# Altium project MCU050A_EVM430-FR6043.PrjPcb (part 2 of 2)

## Sheet MCU050A_HID_Bridge.SchDoc
size 431 x 279 mm; Date: Not shown in title block; ApprovedBy: Not shown in title block; CheckedBy: Not shown in title block; Author: Not shown in title block; CompanyName: Not shown in title block; Engineer: Not shown in title block; Organization: Not shown in title block; Address1: Not shown in title block; Address2: Not shown in title block; Address3: Not shown in title block; Address4: Not shown in title block; DocumentNumber: 1; Revision: Use project parameter SCH_Rev; SheetNumber: 4; SheetTotal: 7; PageSetup: Record=PageOptions¦CenterHorizontal=True¦CenterVertical=True¦PrintScale=1.00¦XCorrection=1.00¦YCorrection=1.00¦PrintKind=0¦BorderSize=5000000¦LeftOffset=0¦BottomOffset=0¦Orientation=2¦PaperLength=1000¦PaperWidth=1000¦Scale=100¦PaperSource=15¦PrintQuality=600¦MediaType=1¦DitherType=10¦PaperKind=Letter¦PrintScaleMode=1
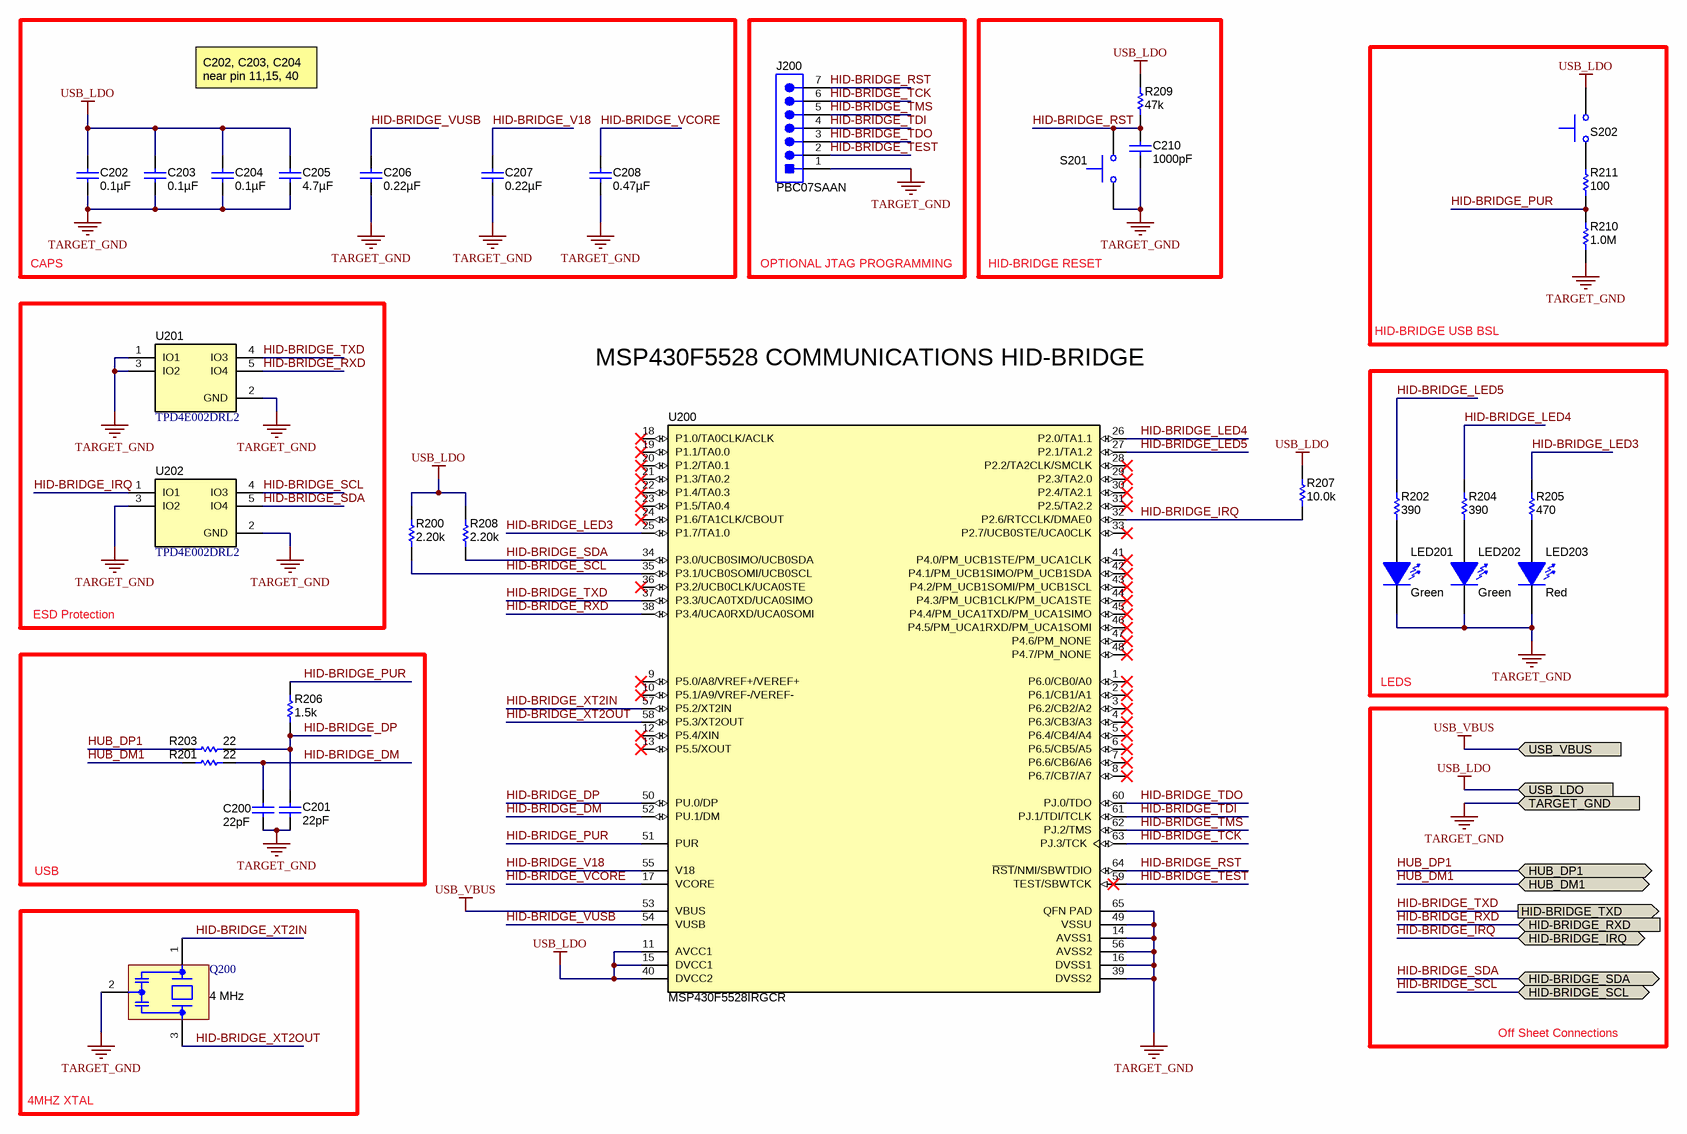
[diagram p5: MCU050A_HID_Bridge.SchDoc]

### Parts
C200  ValueDisplayed: 22pF  [0402S]  (hidden comment: GRM1555C1H220JA01D)
C201  ValueDisplayed: 22pF  [0402S]  (hidden comment: GRM1555C1H220JA01D)
C202  ValueDisplayed: 0.1µF  [0402S]  (hidden comment: GRM155R71C104KA88D)
C203  ValueDisplayed: 0.1µF  [0402S]  (hidden comment: GRM155R71C104KA88D)
C204  ValueDisplayed: 0.1µF  [0402S]  (hidden comment: GRM155R71C104KA88D)
C205  ValueDisplayed: 4.7µF  [0603S]  (hidden comment: GRM188R61A475MAAJ)
C206  ValueDisplayed: 0.22µF  [0402S]  (hidden comment: GRM155R71C224KA12D)
C207  ValueDisplayed: 0.22µF  [0402S]  (hidden comment: GRM155R71C224KA12D)
C208  ValueDisplayed: 0.47µF  [0402S]  (hidden comment: GRM155R61C474KE01)
C210  ValueDisplayed: 1000pF  [0402S]  (hidden comment: GRM1555C1H102JA01D)
J200  PBC07SAAN  [Sullins_xxC07SAAN]
LED201  value Green  [LTST-C191_Green]  (hidden comment: LTST-C191TGKT)
LED202  value Green  [LTST-C191_Green]  (hidden comment: LTST-C191TGKT)
LED203  value Red  [LED_LTST-C190_Red]  (hidden comment: LTST-C190CKT)
Q200  Frequency: 4 MHz  [Murata_CSTCR]  (hidden comment: CSTCR4M00G15L99-R0)
R200  ValueDisplayed: 2.20k  [0402S]  (hidden comment: CRCW04022K20FKED)
R201  ValueDisplayed: 22  [0402S]  (hidden comment: CRCW040222R0JNED)
R202  value 390  [0402S]  (hidden comment: CRCW0402390RJNED)
R203  ValueDisplayed: 22  [0402S]  (hidden comment: CRCW040222R0JNED)
R204  value 390  [0402S]  (hidden comment: CRCW0402390RJNED)
R205  ValueDisplayed: 470  [0402S]  (hidden comment: CRCW0402470RJNED)
R206  ValueDisplayed: 1.5k  [0402S]  (hidden comment: CRCW04021K50JNED)
R207  ValueDisplayed: 10.0k  [0603L]  (hidden comment: RCG060310K0FKEA)
R208  ValueDisplayed: 2.20k  [0402S]  (hidden comment: CRCW04022K20FKED)
R209  value 47k  [0402S]  (hidden comment: CRCW040247K0JNED)
R210  ValueDisplayed: 1.0M  [0402S]  (hidden comment: CRCW04021M00JNED)
R211  ValueDisplayed: 100  [0402S]  (hidden comment: CRCW0402100RJNED)
S201  TL1015AF160QG  [SW_TL1015AF160QG]  (value not drawn)
S202  TL1015AF160QG  [SW_TL1015AF160QG]  (value not drawn)
U200  MSP430F5528IRGCR  [RGC0064B]
U201  TPD4E002DRL2  [DRL0005A]
U202  TPD4E002DRL2  [DRL0005A]

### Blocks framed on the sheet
CAPS: C202-C208
OPTIONAL JTAG PROGRAMMING: J200
HID-BRIDGE RESET: C210 R209 S201
HID-BRIDGE USB BSL: R210 R211 S202
ESD Protection: U201 U202
LEDS: LED201-LED203 R202 R204 R205
USB: C200 C201 R201 R203 R206
4MHZ XTAL: Q200

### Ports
HID-BRIDGE_IRQ (bidir), HID-BRIDGE_RXD (in), HID-BRIDGE_SCL (bidir), HID-BRIDGE_SDA (bidir), HID-BRIDGE_TXD (out), HUB_DM1 (bidir), HUB_DP1 (bidir), TARGET_GND, USB_LDO, USB_VBUS

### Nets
TARGET_GND: C200.2 C201.2 C202.2 C203.2 C204.2 C205.2 C206.2 C207.2 C208.2 C210.2 J200.1 LED201.2(K) LED202.2(K) LED203.2(K) Q200.2(GND) R210.1 S201.1 U200.14(AVSS1) U200.16(DVSS1) U200.39(DVSS2) U200.49(VSSU) U200.56(AVSS2) U200.65(QFN_PAD) U201.1(IO1) U201.2(GND) U201.3(IO2) U202.2(GND) U202.3(IO2) ; port TARGET_GND
USB_LDO: C202.1 C203.1 C204.1 C205.1 R200.2 R207.2 R208.2 R209.2 S202.2 U200.11(AVCC1) U200.15(DVCC1) U200.40(DVCC2) ; port USB_LDO
USB_VBUS: U200.53(VBUS) ; port USB_VBUS
HID-BRIDGE_DM: C200.1 R201.2 U200.52(PU.1/DM)
HID-BRIDGE_DP: C201.1 R203.2 R206.1 U200.50(PU.0/DP)
HID-BRIDGE_IRQ: R207.1 U200.32(P2.6/RTCCLK/DMAE0) U202.1(IO1) ; port HID-BRIDGE_IRQ
HID-BRIDGE_LED3: R205.2 U200.25(P1.7/TA1.0)
HID-BRIDGE_LED4: R204.2 U200.26(P2.0/TA1.1)
HID-BRIDGE_LED5: R202.2 U200.27(P2.1/TA1.2)
HID-BRIDGE_PUR: R206.2 R210.2 R211.1 U200.51(PUR)
HID-BRIDGE_RST: C210.1 J200.7 R209.1 S201.2 U200.64(~{RST}/NMI/SBWTDIO)
HID-BRIDGE_RXD: U200.38(P3.4/UCA0RXD/UCA0SOMI) U201.5(IO4) ; port HID-BRIDGE_RXD
HID-BRIDGE_SCL: R200.1 U200.35(P3.1/UCB0SOMI/UCB0SCL) U202.4(IO3) ; port HID-BRIDGE_SCL
HID-BRIDGE_SDA: R208.1 U200.34(P3.0/UCB0SIMO/UCB0SDA) U202.5(IO4) ; port HID-BRIDGE_SDA
HID-BRIDGE_TCK: J200.6 U200.63(PJ.3/TCK)
HID-BRIDGE_TDI: J200.4 U200.61(PJ.1/TDI/TCLK)
HID-BRIDGE_TDO: J200.3 U200.60(PJ.0/TDO)
HID-BRIDGE_TEST: J200.2 U200.59(TEST/SBWTCK)
HID-BRIDGE_TMS: J200.5 U200.62(PJ.2/TMS)
HID-BRIDGE_TXD: U200.37(P3.3/UCA0TXD/UCA0SIMO) U201.4(IO3) ; port HID-BRIDGE_TXD
HID-BRIDGE_V18: C207.1 U200.55(V18)
HID-BRIDGE_VCORE: C208.1 U200.17(VCORE)
HID-BRIDGE_VUSB: C206.1 U200.54(VUSB)
HID-BRIDGE_XT2IN: Q200.1(In) U200.57(P5.2/XT2IN)
HID-BRIDGE_XT2OUT: Q200.3(Out) U200.58(P5.3/XT2OUT)
HUB_DM1: R201.1 ; port HUB_DM1
HUB_DP1: R203.1 ; port HUB_DP1
NetLED201_1: LED201.1(A) R202.1
NetLED202_1: LED202.1(A) R204.1
NetLED203_1: LED203.1(A) R205.1
NetR211_2: R211.2 S202.1

Not connected (* = marked no-connect by the designer): U200 1(P6.0/CB0/A0)* 2(P6.1/CB1/A1)* 3(P6.2/CB2/A2)* 4(P6.3/CB3/A3)* 5(P6.4/CB4/A4)* 6(P6.5/CB5/A5)* 7(P6.6/CB6/A6)* 8(P6.7/CB7/A7)* 9(P5.0/A8/VREF+/VEREF+)* 10(P5.1/A9/VREF-/VEREF-)* 12(P5.4/XIN)* 13(P5.5/XOUT)* 18(P1.0/TA0CLK/ACLK)* 19(P1.1/TA0.0)* 20(P1.2/TA0.1)* 21(P1.3/TA0.2)* 22(P1.4/TA0.3)* 23(P1.5/TA0.4)* 24(P1.6/TA1CLK/CBOUT)* 28(P2.2/TA2CLK/SMCLK)* 29(P2.3/TA2.0)* 30(P2.4/TA2.1)* 31(P2.5/TA2.2)* 33(P2.7/UCB0STE/UCA0CLK)* 36(P3.2/UCB0CLK/UCA0STE)* 41(P4.0/PM_UCB1STE/PM_UCA1CLK)* 42(P4.1/PM_UCB1SIMO/PM_UCB1SDA)* 43(P4.2/PM_UCB1SOMI/PM_UCB1SCL)* 44(P4.3/PM_UCB1CLK/PM_UCA1STE)* 45(P4.4/PM_UCA1TXD/PM_UCA1SIMO)* 46(P4.5/PM_UCA1RXD/PM_UCA1SOMI)* 47(P4.6/PM_NONE)* 48(P4.7/PM_NONE)*

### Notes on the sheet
- C202, C203, C204
  near pin 11,15, 40
- MSP430F5528 COMMUNICATIONS HID-BRIDGE
- Off Sheet Connections

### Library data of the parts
C200 C201 = GRM1555C1H220JA01D: CAP, CERM, 22 pF, 50 V, +/- 5%, C0G/NP0, 0402; Manufacturer: MuRata; Polarized: N; CompType: Capacitor; Value: 22pF; U/M: EA; Cap_F: 0.000000000022; Tolerance_%: 5; Value1: Unknown; VDC_V: 50; Value2: 50V; TaMin_C: -55; TaMax_C: 125; Cap_Case: 0402; AEC Category: Q200
C202-C204 = GRM155R71C104KA88D: CAP, CERM, 0.1 µF, 16 V, +/- 10%, X7R, 0402; Manufacturer: MuRata; Polarized: N; CompType: Capacitor; Value: 0.1uF; U/M: EA; Cap_F: 0.0000001; Tolerance_%: 10; Value1: Unknown; VDC_V: 16; Value2: 16V; TaMin_C: -55; TaMax_C: 125; Cap_Case: 0402
C205 = GRM188R61A475MAAJ: CAP, CERM, 4.7 µF, 10 V, +/- 20%, X5R, 0603; Manufacturer: MuRata; Polarized: N; CompType: Capacitor; Value: 4.7uF; U/M: EA; Cap_F: 0.0000047; Tolerance_%: 20; Value1: Unknown; VDC_V: 10; Value2: 10V; TaMin_C: -55; TaMax_C: 85; Cap_Case: 0603; AEC Category: Q200
C206 C207 = GRM155R71C224KA12D: CAP, CERM, 0.22 µF, 16 V, +/- 10%, X7R, 0402; Manufacturer: MuRata; Polarized: N; CompType: Capacitor; Value: 0.22uF; U/M: EA; Cap_F: 0.00000022; Tolerance_%: 10; Value1: Unknown; VDC_V: 16; Value2: 16V; TaMin_C: -55; TaMax_C: 125; Cap_Case: 0402
C208 = GRM155R61C474KE01: CAP, CERM, 0.47 µF, 16 V, +/- 10%, X5R, 0402; Manufacturer: MuRata; Polarized: N; CompType: Capacitor; Value: 0.47uF; U/M: EA; Cap_F: 0.00000047; Tolerance_%: 10; Value1: Unknown; VDC_V: 16; Value2: 16V; TaMin_C: -55; TaMax_C: 85; Cap_Case: 0402
C210 = GRM1555C1H102JA01D: CAP, CERM, 1000 pF, 50 V, +/- 5%, C0G/NP0, 0402; Manufacturer: MuRata; Polarized: N; CompType: Capacitor; Value: 1000pF; U/M: EA; Cap_F: 0.000000001; Tolerance_%: 5; Value1: Unknown; VDC_V: 50; Value2: 50V; TaMin_C: -55; TaMax_C: 125; Cap_Case: 0402
J200 = PBC07SAAN: Header, 2.54 mm, 7x1, Gold, TH; Manufacturer: Sullins Connector Solutions; SymbolCreator: a0411947; Pitch_mm: 2.54; Gender: Male; Shrouded: N; Row_Count: 1; Current_A: 3; Voltage_V: 1800; Cert_UL: Y
LED201 LED202 = LTST-C191TGKT: LED, Green, SMD; Manufacturer: Lite-On; Type: InGaN; Vf_V: 3.2; Value2: 3.2V; Io_A: 0.02; Value1: W; U/M: EA
LED203 = LTST-C190CKT: LED, Red, SMD; Manufacturer: Lite-On; Vf_V: 2; Value2: 2V; Io_A: 0.02; Tjmax_C: 85; Power_TotalModule: 0.0625; Value1: 0.0625W; U/M: EA
Q200 = CSTCR4M00G15L99-R0: Resonator, 4MHz, 39pF SMD; Manufacturer: MuRata; SymbolCreator: a0799721; U/M: EA; TaMin_C: 0; TaMax_C: 70; Frequency Stability: ±0.08 %
R200 R208 = CRCW04022K20FKED: RES, 2.20 k, 1%, 0.063 W, 0402; Manufacturer: Vishay-Dale; CompType: Resistor; Res_ohm: 2200; Value_Code: 2k20; Tolerance_%: 1; Power_W: 0.063; Value2: 0.063W; TempCo: 100 ppm/C; U/M: EA; Value: 2.20k; AEC Category: Q200
R201 R203 = CRCW040222R0JNED: RES, 22, 5%, 0.063 W, 0402; Manufacturer: Vishay-Dale; CompType: Resistor; Value: 22; Value_Code: 22R0; Tolerance_%: 5; Power_W: 0.063; Value2: 0.063W; VDC_V: 50; TempCo: 200 ppm/C; EIA_Code: E24; U/M: EA; AEC Category: Q200
R202 R204 = CRCW0402390RJNED: RES, 390 ohm, 5%, 0.063W, 0402; Manufacturer: Vishay-Dale; CompType: Resistor; Value_Code: 390R; Tolerance_%: 5; Power_W: 0.063; VDC_V: 50; TempCo: 200 ppm/C; EIA_Code: E24; U/M: EA
R205 = CRCW0402470RJNED: RES, 470, 5%, 0.063 W, 0402; Manufacturer: Vishay-Dale; CompType: Resistor; Value: 470; Value_Code: 470R; Tolerance_%: 5; Power_W: 0.063; Value2: 0.063W; VDC_V: 50; TempCo: 200 ppm/C; EIA_Code: E24; U/M: EA; AEC Category: Q200
R206 = CRCW04021K50JNED: RES, 1.5 k, 5%, 0.063 W, 0402; Manufacturer: Vishay-Dale; CompType: Resistor; Value: 1.5k; Res_ohm: 1500; Value_Code: 1k50; Tolerance_%: 5; Power_W: 0.063; Value2: 0.063W; VDC_V: 50; TempCo: 200 ppm/C; EIA_Code: E24; U/M: EA
R207 = RCG060310K0FKEA: RES, 10.0 k, 1%, 0.1 W, 0603; Manufacturer: Vishay Draloric; CompType: Resistor; Value: 10.0k; Res_ohm: 10000; Value_Code: 10k0; Tolerance_%: 1; Power_W: 0.1; Value2: 0.1W; VDC_V: 75; TempCo: 100 ppm/C; EIA_Code: E96; U/M: EA; AEC Category: Q200; AEC Qualified: N
R209 = CRCW040247K0JNED: RES, 47 k, 5%, 0.063 W, 0402; Manufacturer: Vishay-Dale; CompType: Resistor; Res_ohm: 47000; Value_Code: 47k0; Tolerance_%: 5; Power_W: 0.063; Value2: 0.063W; VDC_V: 50; TempCo: 200 ppm/C; EIA_Code: E24; U/M: EA
R210 = CRCW04021M00JNED: RES, 1.0 M, 5%, 0.063 W, 0402; Manufacturer: Vishay-Dale; CompType: Resistor; Value: 1.0Meg; Res_ohm: 1000000; Value_Code: 1M00; Tolerance_%: 5; Power_W: 0.063; Value2: 0.063W; VDC_V: 50; TempCo: 200 ppm/C; EIA_Code: E24; U/M: EA
R211 = CRCW0402100RJNED: RES, 100, 5%, 0.063 W, 0402; Manufacturer: Vishay-Dale; CompType: Resistor; Value: 100; Value_Code: 100R; Tolerance_%: 5; Power_W: 0.063; Value2: 0.063W; VDC_V: 50; TempCo: 200 ppm/C; EIA_Code: E24; U/M: EA
S201 S202 = TL1015AF160QG: Switch, Tactile, SPST-NO, 0.05A, 12V, SMT; Manufacturer: E-Switch; SymbolCreator: a0412235; VDC_V: 12; SwitchFunction: Off-Mom; PositionCount: 1; CurrentRating_mA: 50
U200 = MSP430F5528IRGCR: Mixed Signal MicroController, RGC0064B; Manufacturer: Texas Instruments; Alternate PartNumber: MSP430F5528IRGCT; ADC: 12-bit SAR; ADC Channels: 16; Brown Out Reset: Yes; DMA: 3; Eco-Plan: Green (RoHS & no Sb/Br); Flash(KB): 128; Frequency(MHz): 25; GPIO: 47; Multiplier: 32x32; SRAM(B): 8192; SubFamily: 5 Series; Timers - 16-bit: 4; USB: 1; USCI_A (UART/LIN/IrDA/SPI): 2; SymbolCreator: Altium/a0412235; CompType: IC; U/M: EA
U201 U202 = TPD4E002DRL2: Low-Capacitance Array with + / - 15 kV ESD Protection, 4 Channels, -40 to +85 degC, 5-pin SOT (DRL), Green (RoHS & no Sb/Br); Manufacturer: Texas Instruments; Alternate PartNumber: Equivalent; Breakdown Voltage(Min)(V): 6; IEC 61000-4-2 Air-Gap(+/- kV): 15; IO Capacitance(Typ)(pF): 11; IO Leakage Current(nA): 100; SubFamily: ESD Solution

## Sheet MCU050A_USB_Comm-USB_Power.SchDoc
size 431 x 279 mm; Date: Not shown in title block; ApprovedBy: Not shown in title block; CheckedBy: Not shown in title block; Author: Not shown in title block; CompanyName: Not shown in title block; Engineer: Not shown in title block; Organization: Not shown in title block; Address1: Not shown in title block; Address2: Not shown in title block; Address3: Not shown in title block; Address4: Not shown in title block; DocumentNumber: 1; Revision: Use project parameter SCH_Rev; SheetNumber: 5; SheetTotal: 7; PageSetup: Record=PageOptions¦CenterHorizontal=True¦CenterVertical=True¦PrintScale=1.00¦XCorrection=1.00¦YCorrection=1.00¦PrintKind=0¦BorderSize=5000000¦LeftOffset=0¦BottomOffset=0¦Orientation=2¦PaperLength=1000¦PaperWidth=1000¦Scale=100¦PaperSource=15¦PrintQuality=600¦MediaType=1¦DitherType=10¦PaperKind=Letter¦PrintScaleMode=1
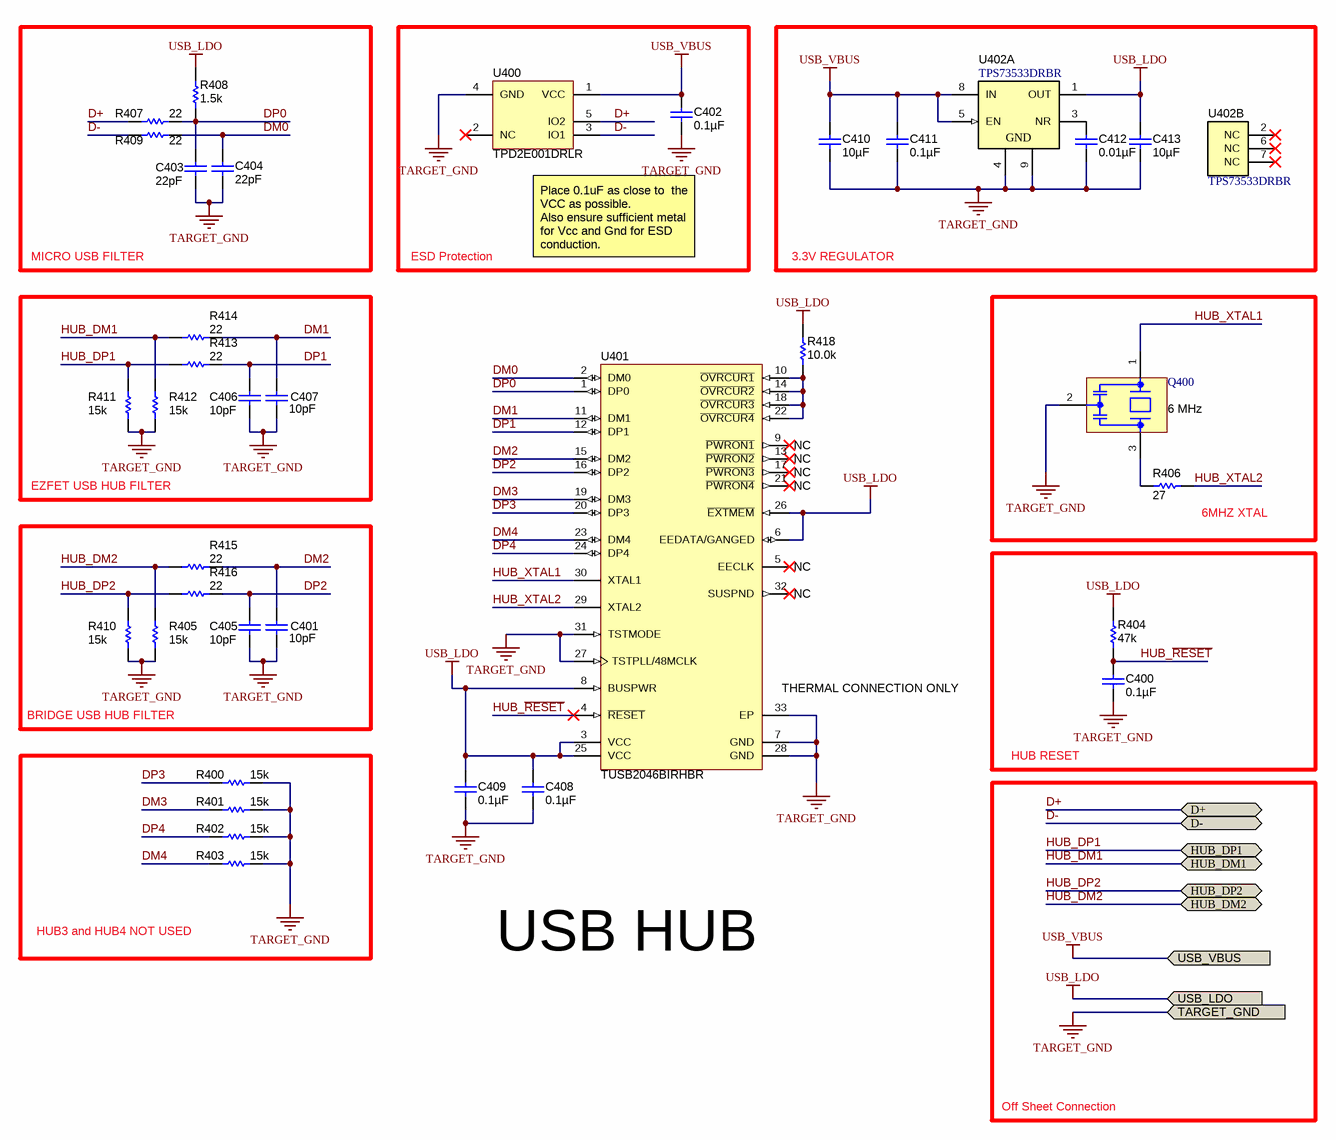
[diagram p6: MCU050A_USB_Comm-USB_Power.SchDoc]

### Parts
C400  ValueDisplayed: 0.1µF  [0402S]  (hidden comment: GRM155R71C104KA88D)
C401  ValueDisplayed: 10pF  [0402S]  (hidden comment: GRM1555C1H100JA01D)
C402  ValueDisplayed: 0.1µF  [0402S]  (hidden comment: GRM155R71C104KA88D)
C403  ValueDisplayed: 22pF  [0402S]  (hidden comment: GRM1555C1H220JA01D)
C404  ValueDisplayed: 22pF  [0402S]  (hidden comment: GRM1555C1H220JA01D)
C405  ValueDisplayed: 10pF  [0402S]  (hidden comment: GRM1555C1H100JA01D)
C406  ValueDisplayed: 10pF  [0402S]  (hidden comment: GRM1555C1H100JA01D)
C407  ValueDisplayed: 10pF  [0402S]  (hidden comment: GRM1555C1H100JA01D)
C408  ValueDisplayed: 0.1µF  [0402S]  (hidden comment: GRM155R71C104KA88D)
C409  ValueDisplayed: 0.1µF  [0402S]  (hidden comment: GRM155R71C104KA88D)
C410  ValueDisplayed: 10µF  [0603S]  (hidden comment: GRM188R61A106ME69D)
C411  ValueDisplayed: 0.1µF  [0402S]  (hidden comment: GRM155R71C104KA88D)
C412  ValueDisplayed: 0.01µF  [0402S]  (hidden comment: GRM155R71C103KA01D)
C413  ValueDisplayed: 10µF  [0603S]  (hidden comment: GRM188R61A106ME69D)
Q400  Frequency: 6 MHz  [Murata_CSTCR]  (hidden comment: CSTCR6M00G53Z-R0)
R400  ValueDisplayed: 15k  [0402S]  (hidden comment: CRCW040215K0JNED)
R401  ValueDisplayed: 15k  [0402S]  (hidden comment: CRCW040215K0JNED)
R402  ValueDisplayed: 15k  [0402S]  (hidden comment: CRCW040215K0JNED)
R403  ValueDisplayed: 15k  [0402S]  (hidden comment: CRCW040215K0JNED)
R404  value 47k  [0402S]  (hidden comment: CRCW040247K0JNED)
R405  ValueDisplayed: 15k  [0402S]  (hidden comment: CRCW040215K0JNED)
R406  value 27  [0402S]  (hidden comment: CRCW040227R0JNED)
R407  value 22  [0402S]  (hidden comment: CRCW040222R0JNED)
R408  value 1.5k  [0402S]  (hidden comment: CRCW04021K50JNED)
R409  value 22  [0402S]  (hidden comment: CRCW040222R0JNED)
R410  ValueDisplayed: 15k  [0402S]  (hidden comment: CRCW040215K0JNED)
R411  ValueDisplayed: 15k  [0402S]  (hidden comment: CRCW040215K0JNED)
R412  ValueDisplayed: 15k  [0402S]  (hidden comment: CRCW040215K0JNED)
R413  value 22  [0402S]  (hidden comment: CRCW040222R0JNED)
R414  value 22  [0402S]  (hidden comment: CRCW040222R0JNED)
R415  value 22  [0402S]  (hidden comment: CRCW040222R0JNED)
R416  value 22  [0402S]  (hidden comment: CRCW040222R0JNED)
R418  ValueDisplayed: 10.0k  [0603L]  (hidden comment: RCG060310K0FKEA)
U400  TPD2E001DRLR  [DRL0005A]
U401  TUSB2046BIRHBR  [RHB0032E]
U402  TPS73533DRBR  [DRB0008A]  (parts A,B of 2)

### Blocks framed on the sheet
MICRO USB FILTER: C403 C404 R407-R409
ESD Protection: C402 U400
3.3V REGULATOR: C410-C413 U402
EZFET USB HUB FILTER: C406 C407 R411-R414
6MHZ XTAL: Q400 R406
BRIDGE USB HUB FILTER: C401 C405 R405 R410 R415 R416
HUB RESET: C400 R404
HUB3 and HUB4 NOT USED: R400-R403

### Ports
D+ (bidir), D- (bidir), HUB_DM1 (bidir), HUB_DM2 (bidir), HUB_DP1 (bidir), HUB_DP2 (bidir), TARGET_GND, USB_LDO, USB_VBUS

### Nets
TARGET_GND: C400.2 C401.2 C402.2 C403.2 C404.2 C405.2 C406.2 C407.2 C408.2 C409.2 C410.2 C411.2 C412.2 C413.2 Q400.2(GND) R400.2 R401.2 R402.2 R403.2 R405.1 R410.1 R411.1 R412.1 U400.4(GND) U401.7(GND) U401.27(TSTPLL/48MCLK) U401.28(GND) U401.31(TSTMODE) U401.33(EP) U402.4(GND) U402.9(GND) ; port TARGET_GND
USB_LDO: C408.1 C409.1 C413.1 R404.2 R408.2 R418.2 U401.3(VCC) U401.6(EEDATA/GANGED) U401.8(BUSPWR) U401.25(VCC) U401.26(~{EXTMEM}) U402.1(OUT) ; port USB_LDO
USB_VBUS: C402.1 C410.1 C411.1 U400.1(VCC) U402.5(EN) U402.8(IN) ; port USB_VBUS
D+: R407.1 U400.5(IO2) ; port D+
D-: R409.1 U400.3(IO1) ; port D-
DM0: C404.1 R409.2 U401.2(DM0)
DM1: C407.1 R414.2 U401.11(DM1)
DM2: C401.1 R415.2 U401.15(DM2)
DM3: R401.1 U401.19(DM3)
DM4: R403.1 U401.23(DM4)
DP0: C403.1 R407.2 R408.1 U401.1(DP0)
DP1: C406.1 R413.2 U401.12(DP1)
DP2: C405.1 R416.2 U401.16(DP2)
DP3: R400.1 U401.20(DP3)
DP4: R402.1 U401.24(DP4)
HUB_DM1: R412.2 R414.1 ; port HUB_DM1
HUB_DM2: R405.2 R415.1 ; port HUB_DM2
HUB_DP1: R411.2 R413.1 ; port HUB_DP1
HUB_DP2: R410.2 R416.1 ; port HUB_DP2
HUB_~{RESET}: C400.1 R404.1 U401.4(~{RESET})
HUB_XTAL1: Q400.1(In) U401.30(XTAL1)
HUB_XTAL2: R406.2 U401.29(XTAL2)
NetC412_1: C412.1 U402.3(NR)
NetQ400_3: Q400.3(Out) R406.1
NetR418_1: R418.1 U401.10(~{OVRCUR1}) U401.14(~{OVRCUR2}) U401.18(~{OVRCUR3}) U401.22(~{OVRCUR4})

Not connected (* = marked no-connect by the designer): U400 2(NC)*; U401 5(EECLK)* 9(~{PWRON1})* 13(~{PWRON2})* 17(~{PWRON3})* 21(~{PWRON4})* 32(SUSPND)*; U402 2(NC)* 6(NC)* 7(NC)*

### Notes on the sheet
- Place 0.1uF as close to  the VCC as possible.
  Also ensure sufficient metal for Vcc and Gnd for ESD conduction.
- (near U401) NC
- (near U401) THERMAL CONNECTION ONLY
- USB HUB
- Off Sheet Connection

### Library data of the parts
C400 C402 C411 = GRM155R71C104KA88D: CAP, CERM, 0.1 µF, 16 V, +/- 10%, X7R, 0402; Manufacturer: MuRata; Polarized: N; CompType: Capacitor; Value: 0.1uF; U/M: EA; Cap_F: 0.0000001; Tolerance_%: 10; Value1: Unknown; VDC_V: 16; Value2: 16V; TaMin_C: -55; TaMax_C: 125; Cap_Case: 0402; AEC Category: Q200
C401 C405-C407 = GRM1555C1H100JA01D: CAP, CERM, 10 pF, 50 V, +/- 5%, C0G/NP0, 0402; Manufacturer: MuRata; Polarized: N; CompType: Capacitor; Value: 10pF; U/M: EA; Cap_F: 0.00000000001; Tolerance_%: 5; Value1: Unknown; VDC_V: 50; Value2: 50V; TaMin_C: -55; TaMax_C: 125; Cap_Case: 0402
C403 C404 = GRM1555C1H220JA01D: CAP, CERM, 22 pF, 50 V, +/- 5%, C0G/NP0, 0402; Manufacturer: MuRata; Polarized: N; CompType: Capacitor; Value: 22pF; U/M: EA; Cap_F: 0.000000000022; Tolerance_%: 5; Value1: Unknown; VDC_V: 50; Value2: 50V; TaMin_C: -55; TaMax_C: 125; Cap_Case: 0402
C408 C409 = GRM155R71C104KA88D: as C202 on sheet MCU050A_HID_Bridge
C410 C413 = GRM188R61A106ME69D: CAP, CERM, 10 µF, 10 V, +/- 20%, X5R, 0603; Manufacturer: MuRata; Polarized: N; CompType: Capacitor; Value: 10uF; U/M: EA; Cap_F: 0.00001; Tolerance_%: 20; Value1: Unknown; VDC_V: 10; Value2: 10V; TaMin_C: -55; TaMax_C: 85; Cap_Case: 0603; AEC Category: Q200; SizeArea_mm2: 1.28; SizeAreaWB_mm2: 4.68; SizeX_mm: 1.6; SizeY_mm: 0.8; SizeZ_mm: 1
C412 = GRM155R71C103KA01D: CAP, CERM, 0.01 µF, 16 V, +/- 10%, X7R, 0402; Manufacturer: MuRata; Polarized: N; CompType: Capacitor; Value: 0.01uF; U/M: EA; Cap_F: 0.00000001; Tolerance_%: 10; Value1: Unknown; VDC_V: 16; Value2: 16V; TaMin_C: -55; TaMax_C: 125; Cap_Case: 0402; AEC Category: Q200; SizeArea_mm2: 0.5; SizeAreaWB_mm2: 3; SizeX_mm: 1; SizeZ_mm: 0.6
Q400 = CSTCR6M00G53Z-R0: Resonator, 6MHz, 15pF SMD; Manufacturer: MuRata; SymbolCreator: a0799721; U/M: EA; TaMin_C: -40; TaMax_C: 125; Frequency Stability: ±0.2 %
R400-R403 R405 R410-R412 = CRCW040215K0JNED: RES, 15 k, 5%, 0.063 W, 0402; Manufacturer: Vishay-Dale; CompType: Resistor; Value: 15k; Res_ohm: 15000; Value_Code: 15k0; Tolerance_%: 5; Power_W: 0.063; Value2: 0.063W; VDC_V: 50; TempCo: 200 ppm/C; EIA_Code: E24; U/M: EA
R404 = CRCW040247K0JNED: as R209 on sheet MCU050A_HID_Bridge
R406 = CRCW040227R0JNED: RES, 27 ohm, 5%, 0.063W, 0402; Manufacturer: Vishay-Dale; CompType: Resistor; Value_Code: 27R0; Tolerance_%: 5; Power_W: 0.063; VDC_V: 50; TempCo: 200 ppm/C; EIA_Code: E24; U/M: EA
R407 R409 R413-R416 = CRCW040222R0JNED: RES, 22 ohm, 5%, 0.063W, 0402; Manufacturer: Vishay-Dale; CompType: Resistor; Value_Code: 22R0; Tolerance_%: 5; Power_W: 0.063; VDC_V: 50; TempCo: 200 ppm/C; EIA_Code: E24; U/M: EA
R408 = CRCW04021K50JNED: RES, 1.5 k, 5%, 0.063 W, 0402; Manufacturer: Vishay-Dale; CompType: Resistor; Res_ohm: 1500; Value_Code: 1k50; Tolerance_%: 5; Power_W: 0.063; Value2: 0.063W; VDC_V: 50; TempCo: 200 ppm/C; EIA_Code: E24; U/M: EA
R418 = RCG060310K0FKEA: as R207 on sheet MCU050A_HID_Bridge
U400 = TPD2E001DRLR: Low-Capacitance + / - 15 kV ESD-Protection Array for High-Speed Data Interfaces, 2 Channels, -40 to +85 degC, 5-pin SOT (DRL), Green (RoHS & no Sb/Br); Manufacturer: Texas Instruments; Alternate Manufacturer: None; Alternate PartNumber: Equivalent; Breakdown Voltage(Min)(V): 11; IEC 61000-4-2 Air-Gap(+/- kV): 15; IEC 61000-4-2 Contact(+/- kV): 8; IO Capacitance(Typ)(pF): 1.5; IO Leakage Current(nA): 1; SubFamily: ESD Solution; USB High Speed: TRUE
U401 = TUSB2046BIRHBR: 4-Port Full-Speed USB Hub, 3.3V, -40 to 85 degC, 32-Pin QFN (RHB), Green (RoHS & no Sb/Br); Manufacturer: Texas Instruments; Alternate Manufacturer: None; Alternate PartNumber: Equivalent; SubFamily: USB Hub Controller; USB Speed: Full; USB Full Speed: True; Supply Voltage(s)(V): 3.3
U402 = TPS73533DRBR: Single Output High PSRR LDO, 500 mA, Fixed 3.3 V Output, 2.7 to 6.5 V Input, with Low IQ, 8-pin SON (DRB), -40 to 125 degC, Green (RoHS & no Sb/Br); Manufacturer: Texas Instruments; Alternate PartNumber: Equivalent; Accuracy(%): 2; Fixed Output Options(V): 3.3; Iout(Max)(A): 0.5; Iq(Typ)(mA): 0.04; SubFamily: Single Channel LDO; Vdo(Typ)(mV): 280; Vin(Max)(V): 6.5; Vin(Min)(V): 2.7

## Sheet MCU050A_ezFET_Lite.SchDoc
size 431 x 279 mm; Date: Not shown in title block; ApprovedBy: Not shown in title block; CheckedBy: Not shown in title block; Author: Not shown in title block; CompanyName: Not shown in title block; Engineer: Not shown in title block; Organization: Not shown in title block; Address1: Not shown in title block; Address2: Not shown in title block; Address3: Not shown in title block; Address4: Not shown in title block; DocumentNumber: 1; Revision: Use project parameter SCH_Rev; SheetNumber: 6; SheetTotal: 7; PageSetup: Record=PageOptions¦CenterHorizontal=True¦CenterVertical=True¦PrintScale=1.00¦XCorrection=1.00¦YCorrection=1.00¦PrintKind=0¦BorderSize=5000000¦LeftOffset=0¦BottomOffset=0¦Orientation=2¦PaperLength=1000¦PaperWidth=1000¦Scale=100¦PaperSource=15¦PrintQuality=600¦MediaType=1¦DitherType=10¦PaperKind=Letter¦PrintScaleMode=1
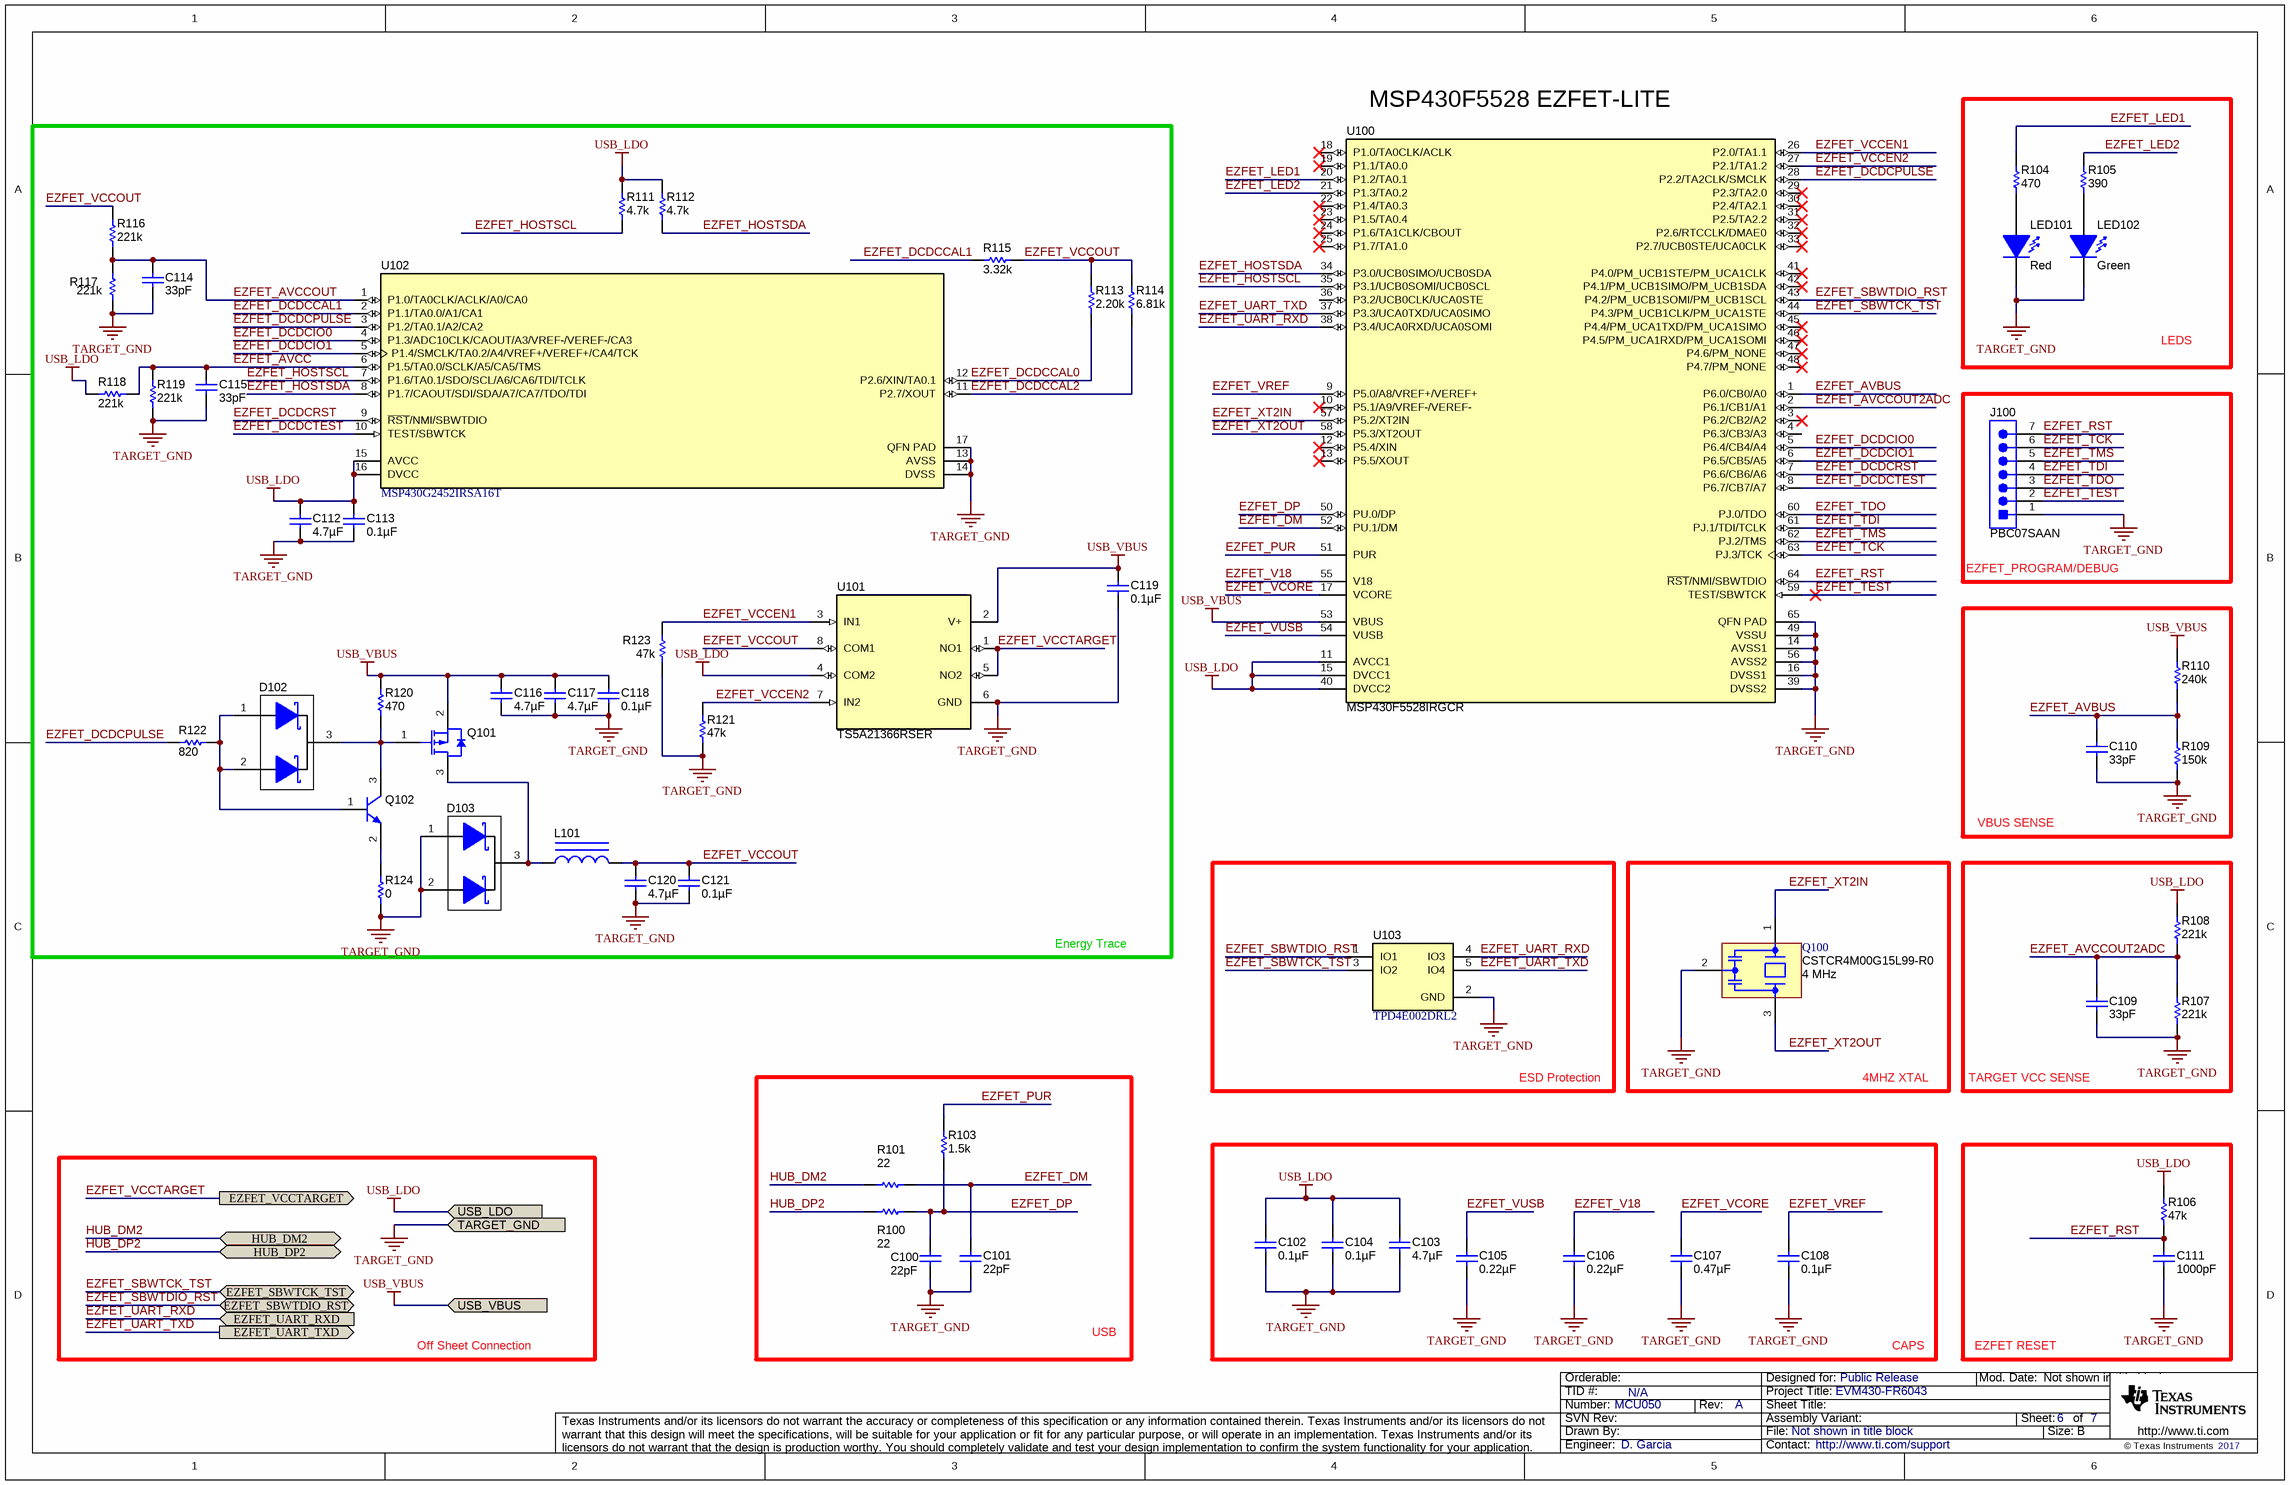
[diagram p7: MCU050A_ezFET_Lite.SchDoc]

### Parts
C100  ValueDisplayed: 22pF  [0402S]  (hidden comment: GRM1555C1H220JA01D)
C101  ValueDisplayed: 22pF  [0402S]  (hidden comment: GRM1555C1H220JA01D)
C102  ValueDisplayed: 0.1µF  [0402S]  (hidden comment: GRM155R71C104KA88D)
C103  ValueDisplayed: 4.7µF  [0603S]  (hidden comment: GRM188R61A475MAAJ)
C104  ValueDisplayed: 0.1µF  [0402S]  (hidden comment: GRM155R71C104KA88D)
C105  ValueDisplayed: 0.22µF  [0402S]  (hidden comment: GRM155R71C224KA12D)
C106  ValueDisplayed: 0.22µF  [0402S]  (hidden comment: GRM155R71C224KA12D)
C107  ValueDisplayed: 0.47µF  [0402S]  (hidden comment: GRM155R61C474KE01)
C108  ValueDisplayed: 0.1µF  [0402S]  (hidden comment: GRM155R71C104KA88D)
C109  ValueDisplayed: 33pF  [0402S]  (hidden comment: GRM1555C1H330JA01D)
C110  ValueDisplayed: 33pF  [0402S]  (hidden comment: GRM1555C1H330JA01D)
C111  ValueDisplayed: 1000pF  [0402S]  (hidden comment: GRM1555C1H102JA01D)
C112  ValueDisplayed: 4.7µF  [0603S]  (hidden comment: GRM188R61A475MAAJ)
C113  ValueDisplayed: 0.1µF  [0402S]  (hidden comment: GRM155R71C104KA88D)
C114  ValueDisplayed: 33pF  [0402S]  (hidden comment: GRM1555C1H330JA01D)
C115  ValueDisplayed: 33pF  [0402S]  (hidden comment: GRM1555C1H330JA01D)
C116  ValueDisplayed: 4.7µF  [0603S]  (hidden comment: GRM188R61A475MAAJ)
C117  ValueDisplayed: 4.7µF  [0603S]  (hidden comment: GRM188R61A475MAAJ)
C118  ValueDisplayed: 0.1µF  [0402S]  (hidden comment: GRM155R71C104KA88D)
C119  ValueDisplayed: 0.1µF  [0402S]  (hidden comment: GRM155R71C104KA88D)
C120  ValueDisplayed: 4.7µF  [0603S]  (hidden comment: GRM188R61A475MAAJ)
C121  ValueDisplayed: 0.1µF  [0402S]  (hidden comment: GRM155R71C104KA88D)
D102  BAS40-05-7-F  [SOT-23]  (value not drawn)
D103  BAS40-05-7-F  [SOT-23]  (value not drawn)
J100  PBC07SAAN  [Sullins_xxC07SAAN]
L101  CIG21L2R2MNE  [0805]  (value not drawn)
LED101  value Red  [LED_LTST-C190_Red]  (hidden comment: LTST-C190CKT)
LED102  value Green  [LTST-C191_Green]  (hidden comment: LTST-C191TGKT)
Q100  CSTCR4M00G15L99-R0  Frequency: 4 MHz  [Murata_CSTCR]
Q101  DMG1013UW  [SOT-323]  (value not drawn)
Q102  BC850CLT1G  [SOT-23]  (value not drawn)
R100  ValueDisplayed: 22  [0402S]  (hidden comment: CRCW040222R0JNED)
R101  ValueDisplayed: 22  [0402S]  (hidden comment: CRCW040222R0JNED)
R103  ValueDisplayed: 1.5k  [0402S]  (hidden comment: CRCW04021K50JNED)
R104  value 470  [0402S]  (hidden comment: CRCW0402470RJNED)
R105  value 390  [0402S]  (hidden comment: CRCW0402390RJNED)
R106  value 47k  [0402S]  (hidden comment: CRCW040247K0JNED)
R107  ValueDisplayed: 221k  [0402S]  (hidden comment: CRCW0402221KFKED)
R108  ValueDisplayed: 221k  [0402S]  (hidden comment: CRCW0402221KFKED)
R109  ValueDisplayed: 150k  [0402S]  (hidden comment: CRCW0402150KFKED)
R110  ValueDisplayed: 240k  [0402S]  (hidden comment: CRCW0402240KFKED)
R111  ValueDisplayed: 4.7k  [0402S]  (hidden comment: CRCW04024K70JNED)
R112  ValueDisplayed: 4.7k  [0402S]  (hidden comment: CRCW04024K70JNED)
R113  ValueDisplayed: 2.20k  [0402S]  (hidden comment: CRCW04022K20FKED)
R114  ValueDisplayed: 6.81k  [0402S]  (hidden comment: CRCW04026K81FKED)
R115  ValueDisplayed: 3.32k  [0402S]  (hidden comment: CRCW04023K32FKED)
R116  ValueDisplayed: 221k  [0402S]  (hidden comment: CRCW0402221KFKED)
R117  ValueDisplayed: 221k  [0402S]  (hidden comment: CRCW0402221KFKED)
R118  ValueDisplayed: 221k  [0402S]  (hidden comment: CRCW0402221KFKED)
R119  ValueDisplayed: 221k  [0402S]  (hidden comment: CRCW0402221KFKED)
R120  ValueDisplayed: 470  [0402S]  (hidden comment: CRCW0402470RJNED)
R121  ValueDisplayed: 47k  [0402S]  (hidden comment: CRCW040247K0JNED)
R122  ValueDisplayed: 820  [0402S]  (hidden comment: CRCW0402820RJNED)
R123  ValueDisplayed: 47k  [0402S]  (hidden comment: CRCW040247K0JNED)
R124  ValueDisplayed: 0  [0402S]  (hidden comment: CRCW04020000Z0ED)
U100  MSP430F5528IRGCR  [RGC0064B]
U101  TS5A21366RSER  [RSE0008A]
U102  MSP430G2452IRSA16T  [RSA0016B]
U103  TPD4E002DRL2  [DRL0005A]

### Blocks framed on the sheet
LEDS: LED101 LED102 R104 R105
Energy Trace: C112-C121 D102 D103 L101 Q101 Q102 R111-R124 U101 U102
EZFET_PROGRAM/DEBUG: J100
VBUS SENSE: C110 R109 R110
ESD Protection: U103
4MHZ XTAL: Q100
TARGET VCC SENSE: C109 R107 R108
USB: C100 C101 R100 R101 R103
CAPS: C102-C108
EZFET RESET: C111 R106

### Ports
EZFET_SBWTCK_TST (bidir), EZFET_SBWTDIO_RST (bidir), EZFET_UART_RXD (in), EZFET_UART_TXD (out), EZFET_VCCTARGET, HUB_DM2 (bidir), HUB_DP2 (bidir), TARGET_GND, USB_LDO, USB_VBUS

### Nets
TARGET_GND: C100.2 C101.2 C102.2 C103.2 C104.2 C105.2 C106.2 C107.2 C108.2 C109.2 C110.2 C111.2 C112.2 C113.2 C114.2 C115.2 C116.2 C117.2 C118.2 C119.2 C120.2 C121.2 D103.1(A) D103.2(K) J100.1 LED101.2(K) LED102.2(K) Q100.2(GND) R107.1 R109.1 R117.1 R119.1 R121.1 R123.1 R124.2 U100.14(AVSS1) U100.16(DVSS1) U100.39(DVSS2) U100.49(VSSU) U100.56(AVSS2) U100.65(QFN_PAD) U101.6(GND) U102.13(AVSS) U102.14(DVSS) U102.17(QFN_PAD) U103.2(GND) ; port TARGET_GND
USB_LDO: C102.1 C103.1 C104.1 C112.1 C113.1 R106.2 R108.2 R111.1 R112.1 R118.1 U100.11(AVCC1) U100.15(DVCC1) U100.40(DVCC2) U101.4(COM2) U102.15(AVCC) U102.16(DVCC) ; port USB_LDO
USB_VBUS: C116.1 C117.1 C118.1 C119.1 Q101.2(S) R110.2 R120.1 U100.53(VBUS) U101.2(V+) ; port USB_VBUS
EZFET_AVBUS: C110.1 R109.2 R110.1 U100.1(P6.0/CB0/A0)
EZFET_AVCC: C115.1 R118.2 R119.2 U102.6(P1.5/TA0.0/SCLK/A5/CA5/TMS)
EZFET_AVCCOUT: C114.1 R116.1 R117.2 U102.1(P1.0/TA0CLK/ACLK/A0/CA0)
EZFET_AVCCOUT2ADC: C109.1 R107.2 R108.1 U100.2(P6.1/CB1/A1)
EZFET_DCDCCAL0: R113.1 U102.12(P2.6/XIN/TA0.1)
EZFET_DCDCCAL1: R115.2 U102.2(P1.1/TA0.0/A1/CA1)
EZFET_DCDCCAL2: R114.1 U102.11(P2.7/XOUT)
EZFET_DCDCIO0: U100.5(P6.4/CB4/A4) U102.4(P1.3/ADC10CLK/CAOUT/A3/VREF-/VEREF-/CA3)
EZFET_DCDCIO1: U100.6(P6.5/CB5/A5) U102.5(P1.4/SMCLK/TA0.2/A4/VREF+/VEREF+/CA4/TCK)
EZFET_DCDCPULSE: R122.2 U100.28(P2.2/TA2CLK/SMCLK) U102.3(P1.2/TA0.1/A2/CA2)
EZFET_DCDCRST: U100.7(P6.6/CB6/A6) U102.9(~{RST}/NMI/SBWTDIO)
EZFET_DCDCTEST: U100.8(P6.7/CB7/A7) U102.10(TEST/SBWTCK)
EZFET_DM: C101.1 R101.2 U100.52(PU.1/DM)
EZFET_DP: C100.1 R100.2 R103.2 U100.50(PU.0/DP)
EZFET_HOSTSCL: R111.2 U100.35(P3.1/UCB0SOMI/UCB0SCL) U102.7(P1.6/TA0.1/SDO/SCL/A6/CA6/TDI/TCLK)
EZFET_HOSTSDA: R112.2 U100.34(P3.0/UCB0SIMO/UCB0SDA) U102.8(P1.7/CAOUT/SDI/SDA/A7/CA7/TDO/TDI)
EZFET_LED1: R104.2 U100.20(P1.2/TA0.1)
EZFET_LED2: R105.2 U100.21(P1.3/TA0.2)
EZFET_PUR: R103.1 U100.51(PUR)
EZFET_RST: C111.1 J100.7 R106.1 U100.64(~{RST}/NMI/SBWTDIO)
EZFET_SBWTCK_TST: U100.44(P4.3/PM_UCB1CLK/PM_UCA1STE) U103.3(IO2) ; port EZFET_SBWTCK_TST
EZFET_SBWTDIO_RST: U100.43(P4.2/PM_UCB1SOMI/PM_UCB1SCL) U103.1(IO1) ; port EZFET_SBWTDIO_RST
EZFET_TCK: J100.6 U100.63(PJ.3/TCK)
EZFET_TDI: J100.4 U100.61(PJ.1/TDI/TCLK)
EZFET_TDO: J100.3 U100.60(PJ.0/TDO)
EZFET_TEST: J100.2 U100.59(TEST/SBWTCK)
EZFET_TMS: J100.5 U100.62(PJ.2/TMS)
EZFET_UART_RXD: U100.38(P3.4/UCA0RXD/UCA0SOMI) U103.4(IO3) ; port EZFET_UART_RXD
EZFET_UART_TXD: U100.37(P3.3/UCA0TXD/UCA0SIMO) U103.5(IO4) ; port EZFET_UART_TXD
EZFET_V18: C106.1 U100.55(V18)
EZFET_VCCEN1: R123.2 U100.26(P2.0/TA1.1) U101.3(IN1)
EZFET_VCCEN2: R121.2 U100.27(P2.1/TA1.2) U101.7(IN2)
EZFET_VCCOUT: C120.1 C121.1 L101.2 R113.2 R114.2 R115.1 R116.2 U101.8(COM1)
EZFET_VCCTARGET: U101.1(NO1) U101.5(NO2) ; port EZFET_VCCTARGET
EZFET_VCORE: C107.1 U100.17(VCORE)
EZFET_VREF: C108.1 U100.9(P5.0/A8/VREF+/VEREF+)
EZFET_VUSB: C105.1 U100.54(VUSB)
EZFET_XT2IN: Q100.1(In) U100.57(P5.2/XT2IN)
EZFET_XT2OUT: Q100.3(Out) U100.58(P5.3/XT2OUT)
HUB_DM2: R101.1 ; port HUB_DM2
HUB_DP2: R100.1 ; port HUB_DP2
NetD102_1: D102.1(A) D102.2(K) Q102.1(B) R122.1
NetD102_3: D102.3(A) Q101.1(G) Q102.3(C) R120.2
NetD103_3: D103.3(A) L101.1 Q101.3(D)
NetLED101_1: LED101.1(A) R104.1
NetLED102_1: LED102.1(A) R105.1
NetQ102_2: Q102.2(E) R124.1

Not connected (* = marked no-connect by the designer): U100 3(P6.2/CB2/A2)* 4(P6.3/CB3/A3) 10(P5.1/A9/VREF-/VEREF-)* 12(P5.4/XIN)* 13(P5.5/XOUT)* 18(P1.0/TA0CLK/ACLK)* 19(P1.1/TA0.0)* 22(P1.4/TA0.3)* 23(P1.5/TA0.4)* 24(P1.6/TA1CLK/CBOUT)* 25(P1.7/TA1.0)* 29(P2.3/TA2.0)* 30(P2.4/TA2.1)* 31(P2.5/TA2.2)* 32(P2.6/RTCCLK/DMAE0)* 33(P2.7/UCB0STE/UCA0CLK)* 36(P3.2/UCB0CLK/UCA0STE) 41(P4.0/PM_UCB1STE/PM_UCA1CLK)* 42(P4.1/PM_UCB1SIMO/PM_UCB1SDA)* 45(P4.4/PM_UCA1TXD/PM_UCA1SIMO)* 46(P4.5/PM_UCA1RXD/PM_UCA1SOMI)* 47(P4.6/PM_NONE)* 48(P4.7/PM_NONE)*

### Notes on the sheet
- (near U100) MSP430F5528 EZFET-LITE
- Off Sheet Connection

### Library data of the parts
C100 C101 = GRM1555C1H220JA01D: as C200 on sheet MCU050A_HID_Bridge
C102 C104 C108 C113 C118 C119 C121 = GRM155R71C104KA88D: as C202 on sheet MCU050A_HID_Bridge
C103 C112 C116 C117 C120 = GRM188R61A475MAAJ: as C205 on sheet MCU050A_HID_Bridge
C105 C106 = GRM155R71C224KA12D: as C206 on sheet MCU050A_HID_Bridge
C107 = GRM155R61C474KE01: as C208 on sheet MCU050A_HID_Bridge
C109 C110 C114 C115 = GRM1555C1H330JA01D: CAP, CERM, 33 pF, 50 V, +/-5%, C0G/NP0, 0402; Manufacturer: MuRata; Polarized: N; CompType: Capacitor; Value: 33pF; U/M: EA; Cap_F: 0.000000000033; Tolerance_%: 5; Value1: Unknown; VDC_V: 50; Value2: 50V; TaMin_C: -55; TaMax_C: 125; Cap_Case: 0402
C111 = GRM1555C1H102JA01D: as C210 on sheet MCU050A_HID_Bridge
D102 D103 = BAS40-05-7-F: Diode, Schottky, 40V, 0.2A, SOT-23; Manufacturer: Diodes Inc.; SymbolCreator: a0412235; U/M: EA; Vf_V: 0.9; Value2: 0.9V; Io_A: 0.2; Vr_V: 40
J100 = PBC07SAAN: as J200 on sheet MCU050A_HID_Bridge
L101 = CIG21L2R2MNE: Inductor, Shielded, Composite, 2.2uH, 0.95A, 0.16 ohm, SMD; Manufacturer: Samsung; Ind_H: 2.2E-6; ValueDisplayed: 2.2µH; Imax_A: 0.95; Irms: 0.95A @ 40C rise; DCR_ohm: 0.16
LED101 = LTST-C190CKT: as LED203 on sheet MCU050A_HID_Bridge
LED102 = LTST-C191TGKT: as LED201 on sheet MCU050A_HID_Bridge
Q100 = CSTCR4M00G15L99-R0: as Q200 on sheet MCU050A_HID_Bridge
Q101 = BSS84W-7-F: MOSFET, P-CH, -50V, -0.13A, SOT-323; Manufacturer: Diodes Inc.; Alternate Manufacturer: None; U/M: EA; ChType: P; VdsMax_V: -50; Value1: 10 ohm; Rdson45_Ohm: 10; Value2: ? nC; Vgs_V: -20; IdsMax_A: -0.13
Q102 = BC850CLT1G, ON Semiconductor: Transistor, NPN, 45V, 0.1A, SOT-23; CompType: BJT; PNP: 0; NPN: 1; Vceo_V: 45; Vcesat1_V: 0.7; Value: 0.7V; IcRated_A: 0.1; HfeMax: 800; TaMin_C: -55; TaMax_C: 150; U/M: EA
R100 R101 = CRCW040222R0JNED: RES, 22, 5%, 0.063 W, 0402; Manufacturer: Vishay-Dale; CompType: Resistor; Value_Code: 22R0; Tolerance_%: 5; Power_W: 0.063; Value2: 0.063W; VDC_V: 50; TempCo: 200 ppm/C; EIA_Code: E24; U/M: EA; Value: 22; AEC Category: Q200
R103 = CRCW04021K50JNED: RES, 1.5 k, 5%, 0.063 W, 0402; Manufacturer: Vishay-Dale; CompType: Resistor; Res_ohm: 1500; Value_Code: 1k50; Tolerance_%: 5; Power_W: 0.063; Value2: 0.063W; VDC_V: 50; TempCo: 200 ppm/C; EIA_Code: E24; U/M: EA; Value: 1.5k
R104 = CRCW0402470RJNED: RES, 470, 5%, 0.063 W, 0402; Manufacturer: Vishay-Dale; CompType: Resistor; Value_Code: 470R; Tolerance_%: 5; Power_W: 0.063; Value2: 0.063W; VDC_V: 50; TempCo: 200 ppm/C; EIA_Code: E24; U/M: EA
R105 = CRCW0402390RJNED: as R202 on sheet MCU050A_HID_Bridge
R106 = CRCW040247K0JNED: as R209 on sheet MCU050A_HID_Bridge
R107 R108 R116-R119 = CRCW0402221KFKED: RES, 221 k, 1%, 0.063 W, 0402; Manufacturer: Vishay-Dale; CompType: Resistor; Res_ohm: 221000; Tolerance_%: 1; Power_W: 0.063; Value2: 0.063W; VDC_V: 50; TempCo: 100 ppm/C; EIA_Code: E96; U/M: EA; Value: 221k; AEC Category: Q200
R109 = CRCW0402150KFKED: RES, 150 k, 1%, 0.063 W, 0402; Manufacturer: Vishay-Dale; CompType: Resistor; Res_ohm: 150000; Tolerance_%: 1; Power_W: 0.063; Value2: 0.063W; VDC_V: 50; TempCo: 100 ppm/C; EIA_Code: E96; U/M: EA; Value: 150k; AEC Category: Q200
R110 = CRCW0402240KFKED: RES, 240 k, 1%, 0.063 W, 0402; Manufacturer: Vishay-Dale; CompType: Resistor; Res_ohm: 240000; Tolerance_%: 1; Power_W: 0.063; Value2: 0.063W; VDC_V: 50; TempCo: 100 ppm/C; U/M: EA; Value: 240k; AEC Category: Q200
R111 R112 = CRCW04024K70JNED: RES, 4.7 k, 5%, 0.063 W, 0402; Manufacturer: Vishay-Dale; CompType: Resistor; Res_ohm: 4700; Value_Code: 4k70; Tolerance_%: 5; Power_W: 0.063; Value2: 0.063W; VDC_V: 50; TempCo: 200 ppm/C; EIA_Code: E24; U/M: EA; Value: 4.7k
R113 = CRCW04022K20FKED: as R200 on sheet MCU050A_HID_Bridge
R114 = CRCW04026K81FKED: RES, 6.81 k, 1%, 0.063 W, 0402; Manufacturer: Vishay-Dale; CompType: Resistor; Res_ohm: 6810; Value_Code: 6k81; Tolerance_%: 1; Power_W: 0.063; Value2: 0.063W; VDC_V: 50; TempCo: 100 ppm/C; EIA_Code: E96; U/M: EA; Value: 6.81k; AEC Category: Q200
R115 = CRCW04023K32FKED: RES, 3.32 k, 1%, 0.063 W, 0402; Manufacturer: Vishay-Dale; CompType: Resistor; Res_ohm: 3320; Value_Code: 3k32; Tolerance_%: 1; Power_W: 0.063; Value2: 0.063W; VDC_V: 50; TempCo: 100 ppm/C; EIA_Code: E96; U/M: EA; Value: 3.32k; AEC Category: Q200
R120 = CRCW0402470RJNED: RES, 470, 5%, 0.063 W, 0402; Manufacturer: Vishay-Dale; CompType: Resistor; Value_Code: 470R; Tolerance_%: 5; Power_W: 0.063; Value2: 0.063W; VDC_V: 50; TempCo: 200 ppm/C; EIA_Code: E24; U/M: EA; Value: 470
R121 R123 = CRCW040247K0JNED: RES, 47 k, 5%, 0.063 W, 0402; Manufacturer: Vishay-Dale; CompType: Resistor; Res_ohm: 47000; Value_Code: 47k0; Tolerance_%: 5; Power_W: 0.063; Value2: 0.063W; VDC_V: 50; TempCo: 200 ppm/C; EIA_Code: E24; U/M: EA; Value: 47k
R122 = CRCW0402820RJNED: RES, 820, 5%, 0.063 W, 0402; Manufacturer: Vishay-Dale; CompType: Resistor; Value_Code: 820R; Tolerance_%: 5; Power_W: 0.063; Value2: 0.063W; VDC_V: 50; TempCo: 200 ppm/C; EIA_Code: E24; U/M: EA; Value: 820
R124 = CRCW04020000Z0ED: RES, 0, 5%, 0.063 W, 0402; Manufacturer: Vishay-Dale; CompType: Resistor; Value_Code: 0000; Tolerance_%: 5; Power_W: 0.063; Value2: 0.063W; VDC_V: 50; TempCo: 200 ppm/C; EIA_Code: E24; U/M: EA; Value: 0
U100 = MSP430F5528IRGCR: as U200 on sheet MCU050A_HID_Bridge
U101 = CMP-0074338-2: 0.75-Ohm DUAL SPST ANALOG SWITCH WITH 1.8-V COMPATIBLE INPUT LOGIC, RSE0008A (UQFN-8); Manufacturer: Texas Instruments; SizeZ_mm: 0.6; SizeX_mm: 1.5; SizeArea_mm2: 2.25; CompType: IC; U/M: EA; SizeAreaWB_mm2: 6.25
U102 = CMP-0039612-1: 16 MHz Mixed Signal Microcontroller with 8 KB Flash, 256 B SRAM and 16 GPIOs, 16-pin QFN (RSA), Green (RoHS & no Sb/Br); Manufacturer: Texas Instruments; GPIO: 16; Cap touch I/O: Yes; SRAM(B): 256; ADC: 10-bit SAR; Timers - 16-bit: 1; USI: "(I2C/SPI)","1"; SubFamily: Value Line; ADC Channels: 8
U103 = TPD4E002DRL2: as U201 on sheet MCU050A_HID_Bridge

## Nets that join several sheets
EZ-FET_VCC: MCU050A_EVM430-FR6043 (J2.1), MCU050A_main (S5.3)
TARGET_GND: MCU050A_EVM430-FR6043 (J2.3 J2.4 J12.5 RUSB.1), MCU050A_main (36 pins), MCU050A_HID_Bridge (28 pins), MCU050A_USB_Comm-USB_Power (31 pins), MCU050A_ezFET_Lite (46 pins)
TARGET_VCC: MCU050A_main (J32.1 S5.2), MCU050A_Analog-Front-End (JP3.2)
USB_LDO: MCU050A_EVM430-FR6043 (J4.3), MCU050A_HID_Bridge (12 pins), MCU050A_USB_Comm-USB_Power (12 pins), MCU050A_ezFET_Lite (16 pins)
USB_VBUS: MCU050A_EVM430-FR6043 (J12.1), MCU050A_HID_Bridge (U200.53), MCU050A_USB_Comm-USB_Power (6 pins), MCU050A_ezFET_Lite (9 pins)
USS_GND: MCU050A_main (13 pins), MCU050A_Analog-Front-End (44 pins)
CH0_IN: MCU050A_main (U1.74), MCU050A_Analog-Front-End (R75.1)
CH0_OUT: MCU050A_main (U1.73), MCU050A_Analog-Front-End (R77.1)
CH1_IN: MCU050A_main (U1.67), MCU050A_Analog-Front-End (R80.1)
CH1_OUT: MCU050A_main (U1.68), MCU050A_Analog-Front-End (R78.1)
COMM_IRQ: MCU050A_EVM430-FR6043 (J1.1), MCU050A_main (U1.31)
COMM_RXD: MCU050A_EVM430-FR6043 (J1.7), MCU050A_main (R56.1)
COMM_SCL: MCU050A_EVM430-FR6043 (J1.3), MCU050A_main (R11.1 R30.1 U1.30)
COMM_SDA: MCU050A_EVM430-FR6043 (J1.5), MCU050A_main (R12.1 R31.1 U1.29)
COMM_TXD: MCU050A_EVM430-FR6043 (J1.9), MCU050A_main (R57.1)
D+: MCU050A_EVM430-FR6043 (J12.3), MCU050A_USB_Comm-USB_Power (R407.1 U400.5)
D-: MCU050A_EVM430-FR6043 (J12.2), MCU050A_USB_Comm-USB_Power (R409.1 U400.3)
EZFET_SBWTCK_TST: MCU050A_EVM430-FR6043 (R126.1), MCU050A_ezFET_Lite (U100.44 U103.3)
EZFET_SBWTDIO_RST: MCU050A_EVM430-FR6043 (R125.1), MCU050A_ezFET_Lite (U100.43 U103.1)
EZFET_UART_RXD: MCU050A_EVM430-FR6043 (R128.1), MCU050A_ezFET_Lite (U100.38 U103.4)
EZFET_UART_TXD: MCU050A_EVM430-FR6043 (R127.1), MCU050A_ezFET_Lite (U100.37 U103.5)
EZFET_VCCTARGET: MCU050A_EVM430-FR6043 (J4.1), MCU050A_ezFET_Lite (U101.1 U101.5)
HID-BRIDGE_IRQ: MCU050A_EVM430-FR6043 (R212.1), MCU050A_HID_Bridge (R207.1 U200.32 U202.1)
HID-BRIDGE_RXD: MCU050A_EVM430-FR6043 (R216.1), MCU050A_HID_Bridge (U200.38 U201.5)
HID-BRIDGE_SCL: MCU050A_EVM430-FR6043 (R213.1), MCU050A_HID_Bridge (R200.1 U200.35 U202.4)
HID-BRIDGE_SDA: MCU050A_EVM430-FR6043 (R214.1), MCU050A_HID_Bridge (R208.1 U200.34 U202.5)
HID-BRIDGE_TXD: MCU050A_EVM430-FR6043 (R215.1), MCU050A_HID_Bridge (U200.37 U201.4)
HUB_DM1: MCU050A_HID_Bridge (R201.1), MCU050A_USB_Comm-USB_Power (R412.2 R414.1)
HUB_DM2: MCU050A_USB_Comm-USB_Power (R405.2 R415.1), MCU050A_ezFET_Lite (R101.1)
HUB_DP1: MCU050A_HID_Bridge (R203.1), MCU050A_USB_Comm-USB_Power (R411.2 R413.1)
HUB_DP2: MCU050A_USB_Comm-USB_Power (R410.2 R416.1), MCU050A_ezFET_Lite (R100.1)
JTAG_RESET: MCU050A_EVM430-FR6043 (J3.1), MCU050A_main (5 pins)
JTAG_RXD: MCU050A_EVM430-FR6043 (J3.5), MCU050A_main (J34.14 R41.1)
JTAG_TEST: MCU050A_EVM430-FR6043 (J3.3), MCU050A_main (J34.8 U1.15)
JTAG_TXD: MCU050A_EVM430-FR6043 (J3.7), MCU050A_main (J34.12 R40.1)
RxEn: MCU050A_main (U1.62), MCU050A_Analog-Front-End (J10.4 R68.2)
RxPwr: MCU050A_main (U1.2), MCU050A_Analog-Front-End (J10.3 R72.2)
RxSel1: MCU050A_main (U1.75), MCU050A_Analog-Front-End (J10.6 R70.2)
RxSel2: MCU050A_main (U1.76), MCU050A_Analog-Front-End (J10.8 R69.1)
Tx5vEn: MCU050A_main (U1.5), MCU050A_Analog-Front-End (J10.1 R73.2)
TxPwr: MCU050A_main (U1.4), MCU050A_Analog-Front-End (J10.7 R71.2)
TxSel: MCU050A_main (U1.3), MCU050A_Analog-Front-End (J10.5)
XPB0: MCU050A_main (U1.55), MCU050A_Analog-Front-End (J10.2 R74.2)

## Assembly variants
001: not fitted C18 FID1 FID2 FID3 R43 R50 R51 R58 R59 R62 R74 R76 R79 R81 Y4
002: not fitted C18 R43 R50 R51 R58 R59 R62 R74 R81 SH-J9 SH-J10 SH-J11 SH-J12 SH-J13 SH-J15 SH-J16 SH-J17 SH-J18 Y4; alternate parts R75 -> CMP-0080092-1, R80 -> CMP-0080092-1, R77 -> CMP-0022902-3, R78 -> CMP-0022902-3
